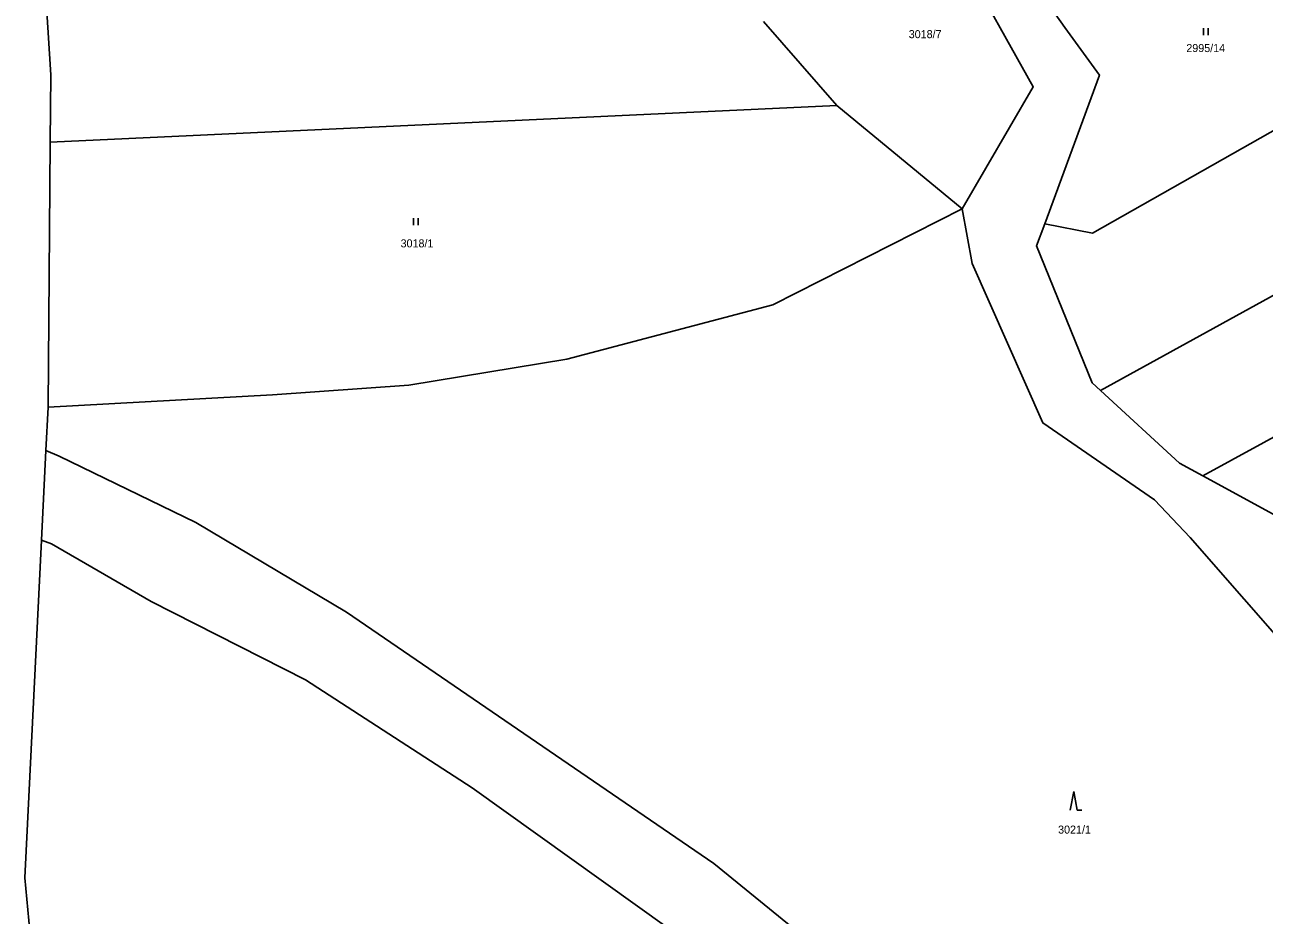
# Model space of a CAD drawing. Extents: x -776734 to -748832, y -1118122 to -976986.
# Drawn here: x -754814.6 to -754552.1, y -1114445.3 to -1114256.9 of the extents above; entities that cross this region are included whole.
import ezdxf

# ---------------------------------------------------------------- set-up
doc = ezdxf.new("R2010")
doc.units = 0
for name, color, linetype in [('KM_Hranice obce', 7, 'Continuous'), ('KM_Hranice parcel', 7, 'Continuous'), ('KM_Parcelní čísla', 7, 'Continuous'), ('KM_Značky kultur', 7, 'Continuous')]:
    doc.layers.add(name, color=color, linetype=linetype)

msp = doc.modelspace()

# ---------------------------------------------------------------- linework, layer by layer
at = {"layer": 'KM_Hranice obce'}
for p, q in [((-754809.2, -1114281.75), (-754809.08, -1114267.47)), ((-754809.65, -1114337.83), (-754809.2, -1114281.75)), ((-754809.65, -1114337.83), (-754810.1, -1114346.97)), ((-754811.04, -1114365.94), (-754810.1, -1114346.97))]:
    msp.add_line(p, q, dxfattribs=at)
for points in [[(-754809.08, -1114267.47), (-754811.14, -1114234.05), (-754812.2, -1114209.06), (-754808.31, -1114183.22), (-754750.8, -1114174)], [(-754793.77, -1114627.29), (-754808.19, -1114505.17), (-754814.57, -1114437.4), (-754811.04, -1114365.94)]]:
    msp.add_lwpolyline(points, dxfattribs=at)
at = {"layer": 'KM_Hranice parcel'}
for p, q in [((-754642.59, -1114273.95), (-754658.16, -1114256.15)), ((-754642.59, -1114273.95), (-754809.2, -1114281.75)), ((-754616.07, -1114295.82), (-754642.59, -1114273.95)), ((-754586.75, -1114334.3), (-754502.28, -1114287.65)), ((-754565.14, -1114352.34), (-754483.92, -1114308.12)), ((-754810.1, -1114346.97), (-754807.32, -1114348.17)), ((-754811.04, -1114365.94), (-754808.91, -1114366.74))]:
    msp.add_line(p, q, dxfattribs=at)
for points in [[(-754616.07, -1114295.82), (-754601.01, -1114270.04), (-754616.35, -1114242.59), (-754603.94, -1114232.22), (-754595.63, -1114232.72), (-754594.61, -1114208.94)], [(-754596.39, -1114254.59), (-754594.35, -1114257.47), (-754587.02, -1114267.55), (-754598.6, -1114299.04)], [(-754598.6, -1114299.04), (-754588.47, -1114300.98), (-754523.34, -1114264.07)], [(-754809.65, -1114337.83), (-754762.1, -1114335.21), (-754733.27, -1114333.13), (-754699.82, -1114327.67), (-754656.15, -1114316.13), (-754616.07, -1114295.82)], [(-754405.85, -1114643.3), (-754427.05, -1114588.83), (-754472.42, -1114532.1), (-754451.7, -1114499.06), (-754481.17, -1114479.15), (-754495.46, -1114444.34), (-754533, -1114405.13), (-754567.8, -1114365.39), (-754575.38, -1114357.4), (-754599.01, -1114341.14), (-754613.96, -1114307.41), (-754616.07, -1114295.82)], [(-754598.6, -1114299.04), (-754600.3, -1114303.66), (-754588.52, -1114332.68), (-754586.75, -1114334.3)], [(-754586.75, -1114334.3), (-754570.08, -1114349.65), (-754565.14, -1114352.34)], [(-754807.32, -1114348.17), (-754778.35, -1114362.22), (-754746.42, -1114381.17), (-754668.64, -1114434.43), (-754621.1, -1114473.12), (-754615.21, -1114477.89), (-754462.5, -1114599.48)], [(-754565.14, -1114352.34), (-754544, -1114363.83), (-754542.43, -1114365.63)], [(-754808.91, -1114366.74), (-754787.81, -1114378.91), (-754755.11, -1114395.52), (-754719.85, -1114418.41), (-754678.1, -1114448.24), (-754628.61, -1114486.03), (-754549.37, -1114550.24), (-754472.04, -1114612.9), (-754464.25, -1114618.78)]]:
    msp.add_lwpolyline(points, dxfattribs=at)
at = {"layer": 'KM_Značky kultur'}
for p, q in [((-754564.981, -1114259.1), (-754564.981, -1114257.6)), ((-754563.98, -1114259.1), (-754563.98, -1114257.6)), ((-754732.251, -1114299.31), (-754732.251, -1114297.81)), ((-754731.25, -1114299.31), (-754731.25, -1114297.81)), ((-754592.46, -1114419.13), (-754593.21, -1114423.13)), ((-754591.71, -1114423.13), (-754592.46, -1114419.13)), ((-754591.71, -1114423.13), (-754590.714, -1114423.13))]:
    msp.add_line(p, q, dxfattribs=at)

# ---------------------------------------------------------------- texts
at = {"layer": 'KM_Parcelní čísla'}
for s, p in [('3018/7', (-754627.39, -1114259.71)), ('2995/14', (-754568.61, -1114262.65)), ('3018/1', (-754734.99, -1114303.99)), ('3021/1', (-754595.76, -1114428.07))]:
    msp.add_text(s, height=1.7, dxfattribs=at).set_placement(p)

doc.saveas('drawing.dxf')
